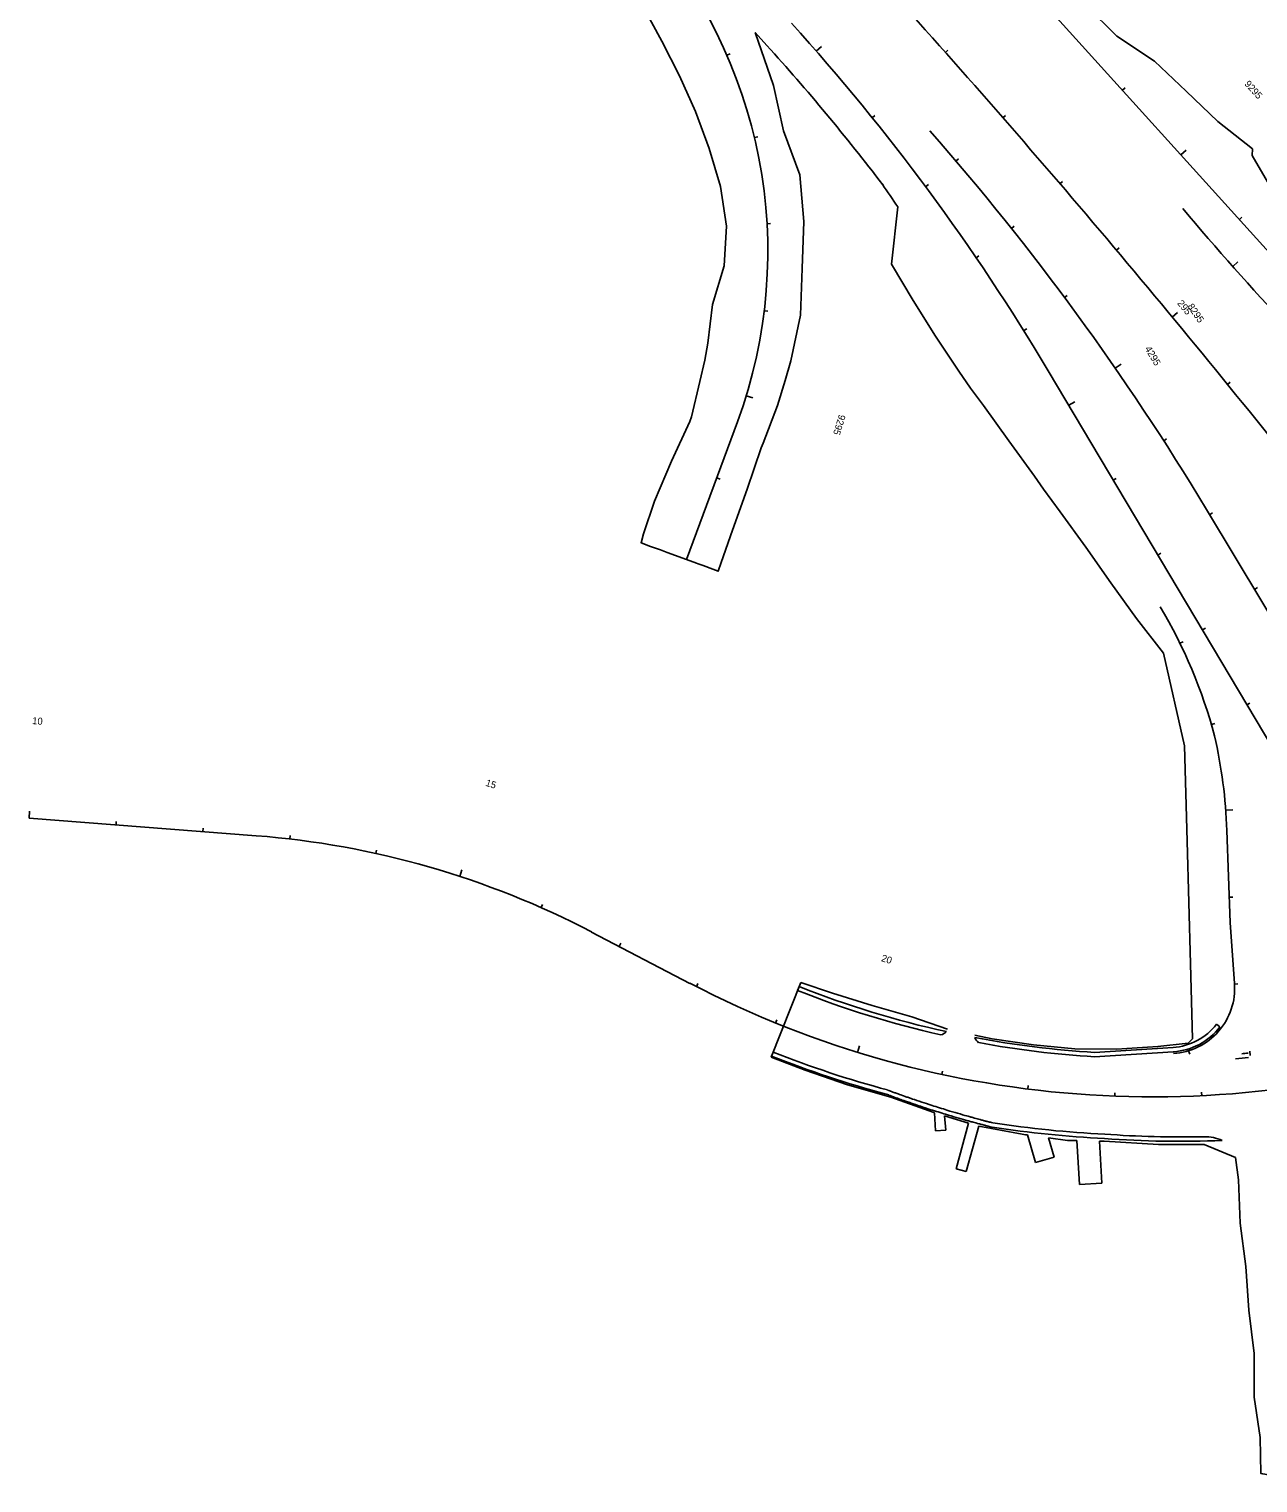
# Model space of a CAD drawing. Extents: x -5665 to 1997148, y 4 to 827579.
# Drawn here: x 1962353 to 1963763, y 803952 to 805620 of the extents above; entities that cross this region are included whole.
import ezdxf

# ---------------------------------------------------------------- set-up
doc = ezdxf.new("R2010")
doc.units = 0
for name, color, linetype in [('RD_HC_CL_Rel', 7, 'Continuous'), ('RD_HC_Data_Tic_Rel', 7, 'Continuous'), ('RD_HC_TX_Rel_Sta50', 7, 'Continuous'), ('RD_PD_CstnLmt', 7, 'Continuous'), ('RD_PD_SW', 7, 'Continuous')]:
    doc.layers.add(name, color=color, linetype=linetype)

msp = doc.modelspace()

# ---------------------------------------------------------------- linework, layer by layer
at = {"layer": 'RD_HC_CL_Rel'}
for p, q in [((1963334.8, 805851.3), (1963783, 805355.8)), ((1963522.1, 805228.1), (1963801.8, 804757.9)), ((1963165.7, 805169.4), (1963107.4, 805011.3)), ((1963703.7, 805069), (1963926.3, 804698.1)), ((1962353.1, 804714.5), (1962613.7, 804694.3)), ((1963727.1, 804700.4), (1963730.8, 804594.9)), ((1963730.8, 804594.9), (1963735.9, 804524.7)), ((1962998.4, 804583.9), (1963111.1, 804525))]:
    msp.add_line(p, q, dxfattribs=at)
for centre, radius, start, end in [((1962635.5, 805364.7), 565, 339.7688, 42.1319), ((1954834, 797986.6), 11459.2, 38.22442, 42.13195), ((1961373.6, 803949.9), 2500, 30.7484, 42.1319), ((1961141.9, 803530.9), 2988, 30.9813, 41.3136), ((1966152.9, 807494.2), 3234, 220.0296, 226.4277), ((1963148.7, 804658.7), 584, 14.9339, 30.7484), ((1963145.1, 804680.1), 582.4, 1.9998, 12.8018), ((1962536.7, 803700.9), 996.5, 62.401, 85.5678), ((1963642, 805540.6), 1145.9, 242.401, 290.3874), ((1963661.1, 804519.3), 75, 273.6667, 4.1175)]:
    msp.add_arc(centre, radius, start, end, dxfattribs=at)
at = {"layer": 'RD_HC_Data_Tic_Rel'}
for p, q in [((1963256, 805595), (1963262, 805600.3)), ((1963404.2, 805593.4), (1963407.2, 805596.1)), ((1963153.5, 805590.3), (1963157.2, 805591.9)), ((1963607.3, 805550.1), (1963610.3, 805552.7)), ((1963320.3, 805518.4), (1963323.4, 805520.9)), ((1963470.3, 805518.4), (1963473.3, 805521)), ((1963185.1, 805495.6), (1963189, 805496.5)), ((1963674.4, 805475.9), (1963680.3, 805481.3)), ((1963416.4, 805468.7), (1963419.4, 805471.3)), ((1963535.7, 805442.7), (1963538.7, 805445.3)), ((1963381.5, 805439.3), (1963384.7, 805441.7)), ((1963199.6, 805396.8), (1963203.6, 805397)), ((1963479.9, 805391.5), (1963483.1, 805394)), ((1963741.5, 805401.7), (1963744.4, 805404.4)), ((1963439.4, 805357.8), (1963442.7, 805360.1)), ((1963600.4, 805366.5), (1963603.5, 805369.1)), ((1963733.8, 805347.9), (1963739.8, 805353.2)), ((1963540.9, 805312.2), (1963544.1, 805314.6)), ((1963196.4, 805297), (1963200.4, 805296.5)), ((1963664.5, 805289.7), (1963670.6, 805294.8)), ((1963494.1, 805274.1), (1963497.5, 805276.2)), ((1963599.1, 805231), (1963605.7, 805235.5)), ((1963727.9, 805212.4), (1963731, 805214.9)), ((1963175.7, 805199.3), (1963183.4, 805196.9)), ((1963545.7, 805188.4), (1963552.6, 805192.5)), ((1963654.7, 805147.8), (1963658, 805150)), ((1963142, 805105.2), (1963145.8, 805103.8)), ((1963596.8, 805102.5), (1963600.3, 805104.5)), ((1963707.4, 805062.8), (1963710.8, 805064.9)), ((1963647.9, 805016.5), (1963651.4, 805018.6)), ((1963758.8, 804977.1), (1963762.3, 804979.2)), ((1963699.1, 804930.6), (1963702.5, 804932.7)), ((1963673.3, 804915.3), (1963676.9, 804917.1)), ((1963750.2, 804844.7), (1963753.6, 804846.7)), ((1963709.4, 804822.2), (1963713.2, 804823.3)), ((1962353.1, 804714.5), (1962353.7, 804722.5)), ((1962452.8, 804706.8), (1962453.1, 804710.8)), ((1963725.9, 804723.7), (1963733.8, 804724.3)), ((1962552.5, 804699.1), (1962552.8, 804703.1)), ((1962652.1, 804690.6), (1962652.6, 804694.6)), ((1962750.7, 804674.1), (1962751.6, 804678)), ((1962847.1, 804647.7), (1962849.6, 804655.3)), ((1962940.4, 804611.9), (1962942, 804615.5)), ((1963729.8, 804623.8), (1963733.8, 804624)), ((1963030, 804567.4), (1963031.8, 804571)), ((1963118.6, 804521.1), (1963120.4, 804524.7)), ((1963735.9, 804524), (1963739.9, 804524.3)), ((1963209.4, 804479.4), (1963211, 804483.1)), ((1963303.6, 804445.7), (1963305.9, 804453.4)), ((1963683.3, 804447.7), (1963684.5, 804443.8)), ((1963400.3, 804420.4), (1963401.1, 804424.3)), ((1963498.8, 804403.6), (1963499.3, 804407.6)), ((1963598.5, 804395.5), (1963598.6, 804399.4)), ((1963698.4, 804396), (1963698.2, 804400))]:
    msp.add_line(p, q, dxfattribs=at)
at = {"layer": 'RD_PD_CstnLmt'}
for p, q in [((1963199.4, 805601.5), (1963186.1, 805616.2)), ((1963342.6, 805350.3), (1963349.6, 805416.2)), ((1963204.3, 804440.1), (1963238.4, 804526)), ((1963274.8, 804513.8), (1963238.4, 804526)), ((1963274.8, 804513.8), (1963320.2, 804499.7)), ((1963320.2, 804499.7), (1963365.9, 804486.4)), ((1963365.9, 804486.4), (1963406.6, 804472.3)), ((1963437.9, 804465.4), (1963458, 804461.4)), ((1963458, 804461.4), (1963505.2, 804454.5)), ((1963505.2, 804454.5), (1963552.8, 804449.8)), ((1963552.8, 804449.8), (1963600.5, 804449.4)), ((1963600.5, 804449.4), (1963648.1, 804452.4)), ((1963682.7, 804456.3), (1963648.1, 804452.4)), ((1963243.2, 804425.4), (1963204.3, 804440.1)), ((1963243.2, 804425.4), (1963292.1, 804408.5)), ((1963292.1, 804408.5), (1963341.8, 804394.5)), ((1963341.8, 804394.5), (1963390.9, 804376.8)), ((1963390.9, 804376.8), (1963391.9, 804376.5)), ((1963403.4, 804372.9), (1963430.9, 804364.5)), ((1963416.7, 804312.2), (1963430.9, 804364.5)), ((1963428.2, 804309.1), (1963442.5, 804361.1)), ((1963442.5, 804361.1), (1963492.3, 804351.8)), ((1963404.9, 804356.5), (1963392.9, 804355.7)), ((1963498.6, 804351), (1963507.7, 804319.3)), ((1963522.4, 804347.8), (1963544.2, 804344.8)), ((1963522.4, 804347.8), (1963528.9, 804325.4)), ((1963557.9, 804294.2), (1963555.1, 804344.5)), ((1963583.8, 804295.6), (1963581.2, 804343.8)), ((1963586.5, 804343.7), (1963648.8, 804340.2)), ((1963528.9, 804325.4), (1963507.7, 804319.3)), ((1963648.8, 804340.2), (1963701.2, 804340.2)), ((1963701.2, 804340.2), (1963736.9, 804325.2)), ((1963428.2, 804309.1), (1963416.7, 804312.2)), ((1963583.8, 804295.6), (1963557.9, 804294.2))]:
    msp.add_line(p, q, dxfattribs=at)
for points in [[(1963057.5, 805645.9), (1963078.9, 805606.5), (1963099.1, 805566.7), (1963117.6, 805525.7), (1963133.2, 805483.2), (1963146.1, 805439.4), (1963153.1, 805394.2), (1963150.5, 805348.4), (1963137, 805304.2), (1963131.9, 805259.6), (1963128.1, 805240.2), (1963122.5, 805215.6), (1963112.8, 805175.1), (1963111.2, 805169.8), (1963090.1, 805124.3), (1963070.4, 805078.3), (1963058.1, 805041), (1963055.1, 805030.6), (1963066.1, 805026.5), (1963077.4, 805022.4), (1963083, 805020.3), (1963084.9, 805019.6), (1963107.4, 805011.3), (1963118.7, 805007.2), (1963120.6, 805006.5), (1963126.2, 805004.4), (1963137.4, 805000.3), (1963143.6, 804998), (1963147.2, 805008.1), (1963160.2, 805045.2), (1963177, 805092.3), (1963192.8, 805139.7), (1963195.1, 805144.8), (1963211.6, 805188.3), (1963220.4, 805216.8), (1963226.8, 805239.5), (1963237.9, 805292), (1963240, 805345.6), (1963241.8, 805399.2), (1963237.3, 805452.8)], [(1963565.5, 805647.1), (1963601.1, 805611.9), (1963644, 805583.3), (1963680.4, 805548.8), (1963716.6, 805514.1), (1963756.4, 805482.7), (1963756.1, 805475.1), (1963779.2, 805435.8)], [(1963237.3, 805452.8), (1963218.6, 805503.6), (1963206.9, 805555.5), (1963186.1, 805616.2)], [(1963342.6, 805350.3), (1963367.2, 805308.6), (1963392.9, 805267.8), (1963419.6, 805227.6), (1963433.2, 805208.2), (1963448, 805188.3), (1963477, 805147.5), (1963506.5, 805106.9), (1963516.8, 805092.3), (1963535.9, 805066.2), (1963565.5, 805025.7), (1963594.1, 804984.5), (1963623.4, 804943.8)], [(1963623.4, 804943.8), (1963654.4, 804904), (1963678.5, 804797.5), (1963681.5, 804688.2), (1963685.3, 804547.2), (1963687.6, 804461.5), (1963682.7, 804456.3)], [(1963391.9, 804376.5), (1963392.9, 804355.7)], [(1963403.4, 804372.9), (1963404.9, 804356.5)], [(1963492.3, 804351.8), (1963496, 804351.3), (1963498.6, 804351)], [(1963544.2, 804344.8), (1963548.7, 804344.7), (1963555.1, 804344.5)], [(1963581.2, 804343.8), (1963586.5, 804343.7)], [(1963736.9, 804325.2), (1963740.5, 804299.5), (1963742.5, 804249.6), (1963748.8, 804199.9), (1963752.4, 804150), (1963758.6, 804100.3), (1963758.6, 804050.2), (1963765.3, 804003.7), (1963766.2, 803962.4), (1963766.9, 803962.3), (1963768.3, 803962), (1963795.9, 803957), (1963823.4, 803951.9), (1963824.9, 803951.6), (1963824.9, 803951.6), (1963840.2, 804002.5), (1963836.6, 804055.8), (1963832.4, 804105.6), (1963827.7, 804155.4), (1963826.7, 804205.5), (1963826.4, 804237.5)]]:
    msp.add_lwpolyline(points, dxfattribs=at)
for centre, radius, start, end in [((1961373.6, 803949.9), 2462, 37.2891, 42.1319), ((1961309.9, 804040.1), 2460.5, 34.0056, 34.7351)]:
    msp.add_arc(centre, radius, start, end, dxfattribs=at)
at = {"layer": 'RD_PD_SW'}
for p, q in [((1963236.5, 804521.3), (1963234.7, 804516.6)), ((1963715.2, 804478.1), (1963719.1, 804475.1)), ((1963206.6, 804446), (1963204.8, 804441.4)), ((1963575.3, 804445.7), (1963665.4, 804451.4)), ((1963575.4, 804440.6), (1963665.7, 804446.4)), ((1963753.5, 804447), (1963753.9, 804442))]:
    msp.add_line(p, q, dxfattribs=at)
for centre, radius, start, end in [((1963642, 805540.6), 1101.9, 248.3103, 257.2657), ((1963642, 805540.6), 1096.9, 248.3103, 257.5395), ((1963661.1, 804519.3), 68, 273.6667, 322.7034), ((1963661.1, 804519.3), 73, 273.6667, 322.7034), ((1963394.7, 804480.1), 15, 286.9953, 314.9755), ((1963452, 804468.4), 15, 202.1143, 230.2794), ((1963642, 805540.6), 1096.9, 259.2915, 266.519), ((1963642, 805540.6), 1182.9, 248.3103, 255.03), ((1963642, 805540.6), 1177.9, 248.3103, 255.0414), ((1963642, 805540.6), 1101.9, 259.5687, 266.5353), ((1963616.7, 805536.3), 1099.6, 276.6562, 277.0498), ((1963616.7, 805536.3), 1104.6, 276.2624, 277.0365), ((1963642, 805540.6), 1194.9, 261.1294, 267.3534), ((1963642, 805540.6), 1189.9, 261.1409, 267.3534), ((1963674.5, 805543.9), 1200.2, 265.8079, 272.2609), ((1963674.5, 805543.9), 1195.2, 265.8014, 271.2604), ((1963701.9, 804301), 48, 65.3719, 91.2604)]:
    msp.add_arc(centre, radius, start, end, dxfattribs=at)
for points in [[(1963457.7, 804359.9), (1963455.9, 804360.4), (1963454.4, 804360.8), (1963452.4, 804361.3), (1963451.8, 804361.4), (1963450.5, 804361.8), (1963448.6, 804362.3), (1963446.7, 804362.8), (1963444.1, 804363.4), (1963442.9, 804363.8), (1963439.1, 804364.8), (1963436.5, 804365.5), (1963431.4, 804366.9), (1963428.9, 804367.6), (1963416.2, 804371.2), (1963406.1, 804374.2), (1963386, 804380.5), (1963376, 804383.8), (1963363.5, 804388.1), (1963361, 804388.9), (1963356, 804390.7), (1963353.5, 804391.5), (1963349.8, 804392.9), (1963348.6, 804393.3), (1963346.1, 804394.2), (1963344.9, 804394.7), (1963342.4, 804395.6), (1963341.1, 804396), (1963338.7, 804396.9), (1963337.5, 804397.3), (1963336.4, 804397.8)], [(1963458.7, 804364.8), (1963457.3, 804365.2), (1963455.9, 804365.5), (1963454, 804366), (1963453.4, 804366.2), (1963452.1, 804366.5), (1963451.4, 804366.7), (1963449.5, 804367.2), (1963448.2, 804367.5), (1963445.7, 804368.2), (1963444.4, 804368.5), (1963440.6, 804369.6), (1963438.1, 804370.3), (1963433, 804371.7), (1963430.4, 804372.4), (1963417.8, 804376), (1963407.6, 804379), (1963387.5, 804385.3), (1963377.5, 804388.6), (1963365, 804392.8), (1963362.5, 804393.7), (1963357.5, 804395.4), (1963355.1, 804396.3), (1963351.3, 804397.6), (1963350.1, 804398.1), (1963347.6, 804399), (1963346.4, 804399.4), (1963343.9, 804400.3), (1963342.7, 804400.8), (1963340.2, 804401.7), (1963339.1, 804402.1), (1963337.9, 804402.5)]]:
    msp.add_open_spline(points, degree=3, dxfattribs=at)

# ---------------------------------------------------------------- texts
at = {"layer": 'RD_HC_TX_Rel_Sta50'}
for s, rotation, p in [('9295', 312.1319, (1963746.8, 805556.8)), ('295', 309.592, (1963669.8, 805305.2)), ('8295', 304.6786, (1963681.5, 805301.8)), ('4295', 300.7484, (1963632.7, 805253.4)), ('9295', 252.9717, (1963282.3, 805178.5)), ('10', 355.5678, (1962356.5, 804822.6)), ('15', 341.8509, (1962876.1, 804751.9)), ('20', 342.8257, (1963330.1, 804550.6))]:
    msp.add_text(s, height=8, rotation=rotation, dxfattribs=at).set_placement(p)

doc.saveas('drawing.dxf')
